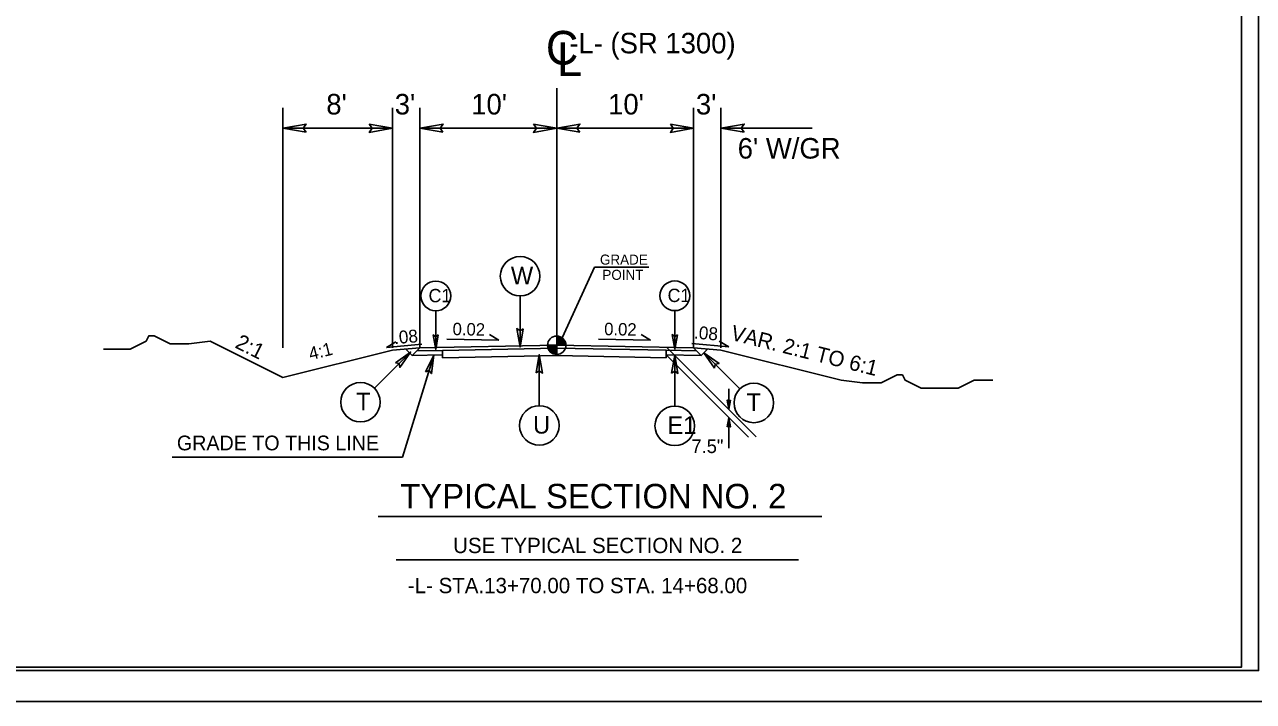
# Model space of a CAD drawing. Extents: x 1818040 to 1825768, y 638918 to 648046.
# Drawn here: x 1821171 to 1822069, y 645383 to 645878 of the extents above; entities that cross this region are included whole.
import ezdxf

# ---------------------------------------------------------------- set-up
doc = ezdxf.new("R2010")
doc.units = 0
for name, color, linetype in [('Old_Level_1', 7, 'Continuous'), ('Prop Dimension', 7, 'Continuous'), ('Prop Dimension Text', 7, 'Continuous'), ('Sheet Plot Border Inside CELL', 7, 'Continuous'), ('Sheet Plot Border Outside CELL', 7, 'Continuous'), ('Sheet Typical CELL', 7, 'Continuous'), ('Typical Grade Point Symbol CELL', 7, 'Continuous'), ('Typical ID Circle CELL', 7, 'Continuous'), ('Typical Pavement Slope CELL', 7, 'Continuous'), ('Typical Pavement Slope Information CELL', 7, 'Continuous'), ('Typical Shoulder Slope CELL', 7, 'Continuous'), ('Typical Slope Point Local CELL', 7, 'Continuous'), ('Typical Terminator CELL', 7, 'Continuous'), ('Typical Text Centerline CELL', 7, 'Continuous'), ('Typical Text General CELL', 7, 'Continuous'), ('Typical Text Grade Point CELL', 7, 'Continuous'), ('Typical Text ID Circle CELL', 7, 'Continuous'), ('Typical Text Label CELL', 7, 'Continuous')]:
    doc.layers.add(name, color=color, linetype=linetype)

msp = doc.modelspace()

# ---------------------------------------------------------------- linework, layer by layer
at = {"layer": 'Old_Level_1'}
for p, q in [((1821359.76, 645641.59), (1821359.76, 645817.04)), ((1821459.76, 645641.59), (1821454.23, 645636.06)), ((1821476.24, 645639.84), (1821559.76, 645641.51)), ((1821639.72, 645639.91), (1821559.76, 645641.51)), ((1821640.27, 645641.96), (1821705.42, 645576.81)), ((1821659.76, 645641.59), (1821665.29, 645636.06)), ((1821469.96, 645636.39), (1821447.16, 645561.85)), ((1821454.23, 645636.06), (1821449.55, 645640.74)), ((1821454.23, 645636.06), (1821476.24, 645636.5)), ((1821457.63, 645639.46), (1821476.24, 645639.84)), ((1821476.24, 645639.84), (1821476.24, 645634.41)), ((1821476.24, 645634.41), (1821559.76, 645636.08)), ((1821639.72, 645634.48), (1821559.76, 645636.08)), ((1821661.89, 645639.46), (1821639.72, 645639.91)), ((1821639.72, 645639.91), (1821639.72, 645634.48)), ((1821639.72, 645636.57), (1821699.84, 645576.45)), ((1821665.29, 645636.06), (1821639.72, 645636.57)), ((1821665.29, 645636.06), (1821669.97, 645640.74)), ((1821685.49, 645611.63), (1821685.49, 645596.8)), ((1821685.49, 645590.68), (1821685.49, 645568.36)), ((1821447.16, 645561.85), (1821278.76, 645561.85))]:
    msp.add_line(p, q, dxfattribs=at)
at = {"layer": 'Prop Dimension'}
for p, q in [((1821559.76, 645643.59), (1821559.76, 645831.25)), ((1821439.76, 645641.59), (1821439.76, 645817.04)), ((1821459.76, 645641.59), (1821459.76, 645817.04)), ((1821659.76, 645641.59), (1821659.76, 645817.04)), ((1821679.76, 645641.59), (1821679.76, 645817.04)), ((1821439.76, 645802.04), (1821359.76, 645802.04)), ((1821559.76, 645802.04), (1821459.76, 645802.04)), ((1821559.76, 645802.04), (1821659.76, 645802.04)), ((1821679.76, 645802.04), (1821746.29, 645802.04))]:
    msp.add_line(p, q, dxfattribs=at)
at = {"layer": 'Sheet Plot Border Inside CELL'}
msp.add_lwpolyline([(1822072.43, 646461.05), (1820405.93, 646461.05), (1820405.93, 645405.95), (1822072.43, 645405.95)], close=True, dxfattribs=at)
at = {"layer": 'Sheet Plot Border Outside CELL'}
msp.add_lwpolyline([(1822076.93, 646483.5), (1820392.93, 646483.5), (1820392.93, 645383.5), (1822076.93, 645383.5)], close=True, dxfattribs=at)
at = {"layer": 'Sheet Typical CELL'}
msp.add_line((1820392.93, 645383.5), (1822076.93, 645383.5), dxfattribs=at)
msp.add_lwpolyline([(1822059.93, 646458.5), (1820559.93, 646458.5), (1820559.93, 645408.5), (1822059.93, 645408.5)], close=True, dxfattribs=at)
at = {"layer": 'Typical Grade Point Symbol CELL'}
for p, q in [((1821559.76, 645643.59), (1821559.76, 645650.3)), ((1821553.05, 645643.59), (1821559.76, 645643.59)), ((1821559.74, 645636.88), (1821559.76, 645643.59)), ((1821559.76, 645643.59), (1821559.74, 645636.88)), ((1821566.47, 645643.59), (1821559.76, 645643.59))]:
    msp.add_line(p, q, dxfattribs=at)
for points in [[(1821559.82, 645650.3), (1821559.82, 645650.3), (1821559.82, 645643.59)], [(1821559.95, 645650.3), (1821559.95, 645643.59)], [(1821560.09, 645650.29), (1821560.09, 645643.59)], [(1821560.22, 645650.29), (1821560.22, 645643.59)], [(1821560.36, 645650.27), (1821560.36, 645643.59)], [(1821560.49, 645650.26), (1821560.49, 645643.59)], [(1821560.63, 645650.24), (1821560.63, 645643.59)], [(1821560.76, 645650.23), (1821560.76, 645643.59)], [(1821560.89, 645650.22), (1821560.89, 645643.59)], [(1821561.03, 645650.19), (1821561.03, 645643.59)], [(1821561.16, 645650.15), (1821561.16, 645643.59)], [(1821561.3, 645650.13), (1821561.3, 645643.59)], [(1821561.43, 645650.1), (1821561.43, 645643.59)], [(1821561.56, 645650.05), (1821561.56, 645643.59)], [(1821561.7, 645650.02), (1821561.7, 645643.59)], [(1821561.83, 645649.98), (1821561.83, 645643.59)], [(1821561.97, 645649.93), (1821561.97, 645643.59)], [(1821562.1, 645649.89), (1821562.1, 645643.59)], [(1821562.24, 645649.83), (1821562.24, 645643.59)], [(1821562.37, 645649.77), (1821562.37, 645643.59)], [(1821553.08, 645643.59), (1821553.08, 645642.86)], [(1821553.21, 645643.59), (1821553.21, 645642.07)], [(1821553.34, 645643.59), (1821553.34, 645641.59)], [(1821553.48, 645643.59), (1821553.48, 645641.19)], [(1821553.61, 645643.59), (1821553.61, 645640.88)], [(1821553.75, 645643.59), (1821553.75, 645640.59)], [(1821553.88, 645643.59), (1821553.88, 645640.34)], [(1821554.02, 645643.59), (1821554.02, 645640.1)], [(1821554.15, 645643.59), (1821554.15, 645639.89)], [(1821554.28, 645643.59), (1821554.28, 645639.7)], [(1821554.42, 645643.59), (1821554.42, 645639.52)], [(1821554.55, 645643.59), (1821554.55, 645639.35)], [(1821554.69, 645643.59), (1821554.69, 645639.19)], [(1821554.82, 645643.59), (1821554.82, 645639.04)], [(1821554.96, 645643.59), (1821554.96, 645638.89)], [(1821555.09, 645643.59), (1821555.09, 645638.76)], [(1821555.22, 645643.59), (1821555.22, 645638.64)], [(1821555.36, 645643.59), (1821555.36, 645638.52)], [(1821555.49, 645643.59), (1821555.49, 645638.4)], [(1821555.63, 645643.59), (1821555.63, 645638.29)], [(1821555.76, 645643.59), (1821555.76, 645638.19)], [(1821555.9, 645643.59), (1821555.9, 645638.1)], [(1821556.03, 645643.59), (1821556.03, 645638.01)], [(1821556.16, 645643.59), (1821556.16, 645637.92)], [(1821556.3, 645643.59), (1821556.3, 645637.83)], [(1821556.43, 645643.59), (1821556.43, 645637.76)], [(1821556.57, 645643.59), (1821556.57, 645637.68)], [(1821556.7, 645643.59), (1821556.7, 645637.61)], [(1821556.84, 645643.59), (1821556.84, 645637.55)], [(1821556.97, 645643.59), (1821556.97, 645637.49)], [(1821557.1, 645643.59), (1821557.1, 645637.43)], [(1821557.24, 645643.59), (1821557.24, 645637.37)], [(1821557.37, 645643.59), (1821557.37, 645637.31)], [(1821557.51, 645643.59), (1821557.51, 645637.26)], [(1821557.64, 645643.59), (1821557.64, 645637.22)], [(1821557.78, 645643.59), (1821557.78, 645637.18)], [(1821557.91, 645643.59), (1821557.91, 645637.15)], [(1821558.04, 645643.59), (1821558.04, 645637.1)], [(1821558.18, 645643.59), (1821558.18, 645637.07)], [(1821558.31, 645643.59), (1821558.31, 645637.04)], [(1821558.45, 645643.59), (1821558.45, 645637.01)], [(1821558.58, 645643.59), (1821558.58, 645636.98)], [(1821558.72, 645643.59), (1821558.72, 645636.97)], [(1821558.85, 645643.59), (1821558.85, 645636.94)], [(1821558.98, 645643.59), (1821558.98, 645636.92)], [(1821559.12, 645643.59), (1821559.12, 645636.91)], [(1821559.25, 645643.59), (1821559.25, 645636.89)], [(1821559.39, 645643.59), (1821559.39, 645636.89)], [(1821559.52, 645643.59), (1821559.52, 645636.88)], [(1821559.66, 645643.59), (1821559.66, 645636.88), (1821559.66, 645636.88)], [(1821562.51, 645649.71), (1821562.51, 645643.59)], [(1821562.64, 645649.65), (1821562.64, 645643.59)], [(1821562.77, 645649.59), (1821562.77, 645643.59)], [(1821562.91, 645649.51), (1821562.91, 645643.59)], [(1821563.04, 645649.44), (1821563.04, 645643.59)], [(1821563.18, 645649.36), (1821563.18, 645643.59)], [(1821563.31, 645649.29), (1821563.31, 645643.59)], [(1821563.44, 645649.2), (1821563.44, 645643.59)], [(1821563.58, 645649.11), (1821563.58, 645643.59)], [(1821563.71, 645649.01), (1821563.71, 645643.59)], [(1821563.85, 645648.92), (1821563.85, 645643.59)], [(1821563.98, 645648.81), (1821563.98, 645643.59)], [(1821564.12, 645648.69), (1821564.12, 645643.59)], [(1821564.25, 645648.57), (1821564.25, 645643.59)], [(1821564.38, 645648.45), (1821564.38, 645643.59)], [(1821564.52, 645648.32), (1821564.52, 645643.59)], [(1821564.65, 645648.19), (1821564.65, 645643.59)], [(1821564.79, 645648.04), (1821564.79, 645643.59)], [(1821564.92, 645647.87), (1821564.92, 645643.59)], [(1821565.06, 645647.71), (1821565.06, 645643.59)], [(1821565.19, 645647.53), (1821565.19, 645643.59)], [(1821565.33, 645647.34), (1821565.33, 645643.59)], [(1821565.46, 645647.13), (1821565.46, 645643.59)], [(1821565.59, 645646.9), (1821565.59, 645643.59)], [(1821565.73, 645646.66), (1821565.73, 645643.59)], [(1821565.86, 645646.38), (1821565.86, 645643.59)], [(1821566, 645646.07), (1821566, 645643.59)], [(1821566.13, 645645.69), (1821566.13, 645643.59)], [(1821566.26, 645645.23), (1821566.26, 645643.59)], [(1821566.4, 645644.55), (1821566.4, 645643.59)]]:
    msp.add_lwpolyline(points, dxfattribs=at)
msp.add_circle((1821559.75, 645643.59), 6.71, dxfattribs=at)
for start, end in [(359.99048, 89.99048), (179.99048, 269.99048)]:
    msp.add_arc((1821559.75, 645643.59), 6.71, start, end, dxfattribs=at)
at = {"layer": 'Typical ID Circle CELL'}
for p, q in [((1821532.99, 645679.56), (1821532.99, 645642.28)), ((1821471.45, 645668.68), (1821471.45, 645640.57)), ((1821646.06, 645668.86), (1821646.06, 645640.75)), ((1821426.6, 645612.18), (1821452.97, 645638.54)), ((1821547.06, 645599.43), (1821547.06, 645633.88)), ((1821645.96, 645599.17), (1821645.96, 645633.62)), ((1821693.55, 645611.64), (1821667.18, 645638))]:
    msp.add_line(p, q, dxfattribs=at)
for centre, radius in [((1821532.99, 645693.98), 14.43), ((1821471.45, 645679.56), 10.88), ((1821646.06, 645679.73), 10.88), ((1821416.41, 645601.97), 14.43), ((1821703.74, 645601.44), 14.43), ((1821547.06, 645585.01), 14.43), ((1821645.96, 645584.75), 14.43)]:
    msp.add_circle(centre, radius, dxfattribs=at)
at = {"layer": 'Typical Pavement Slope CELL'}
for p in [(1821459.76, 645641.59), (1821659.76, 645641.59)]:
    msp.add_line(p, (1821559.76, 645643.59), dxfattribs=at)
at = {"layer": 'Typical Pavement Slope Information CELL'}
for p, q in [((1821517.45, 645647.34), (1821510.69, 645651.42)), ((1821628.18, 645647.34), (1821621.42, 645651.42)), ((1821435.43, 645641.89), (1821442.33, 645646.06)), ((1821461.26, 645644.39), (1821435.43, 645641.89)), ((1821517.45, 645647.34), (1821479.48, 645648.1)), ((1821628.18, 645647.34), (1821590.2, 645648.1)), ((1821685.38, 645642.36), (1821658.5, 645644.96)), ((1821685.38, 645642.36), (1821678.49, 645646.53))]:
    msp.add_line(p, q, dxfattribs=at)
at = {"layer": 'Typical Shoulder Slope CELL'}
for p, q in [((1821439.76, 645639.92), (1821459.76, 645641.59)), ((1821679.76, 645639.92), (1821659.76, 645641.59))]:
    msp.add_line(p, q, dxfattribs=at)
at = {"layer": 'Typical Slope Point Local CELL'}
for p, q in [((1821306.56, 645646.52), (1821359.76, 645619.92)), ((1821439.76, 645639.92), (1821359.76, 645619.92)), ((1821679.76, 645639.92), (1821767.51, 645617.99))]:
    msp.add_line(p, q, dxfattribs=at)
for points in [[(1821306.56, 645646.52), (1821291, 645644.59), (1821287.11, 645644.59), (1821281.27, 645644.59), (1821277.38, 645644.59), (1821273.49, 645646.52), (1821269.6, 645648.48), (1821265.71, 645650.43), (1821261.82, 645650.43), (1821259.86, 645646.52), (1821255.97, 645644.59), (1821252.08, 645642.63), (1821248.19, 645640.7), (1821244.3, 645640.7), (1821240.41, 645640.7), (1821236.52, 645640.7), (1821232.63, 645640.7), (1821228.74, 645640.7)], [(1821767.51, 645617.99), (1821783.07, 645616.05), (1821786.96, 645616.05), (1821792.8, 645616.05), (1821796.69, 645616.05), (1821800.58, 645617.99), (1821804.47, 645619.94), (1821808.36, 645621.89), (1821812.25, 645621.89), (1821814.21, 645617.99), (1821818.1, 645616.05), (1821821.99, 645614.1), (1821825.88, 645612.16), (1821829.77, 645612.16), (1821833.66, 645612.16), (1821837.55, 645612.16), (1821841.44, 645612.16), (1821845.33, 645612.16), (1821849.22, 645612.16), (1821853.11, 645612.16), (1821857, 645614.1), (1821860.89, 645616.05), (1821864.78, 645617.99), (1821870.62, 645617.99), (1821874.51, 645617.99), (1821878.4, 645617.99)]]:
    msp.add_lwpolyline(points, dxfattribs=at)
at = {"layer": 'Typical Terminator CELL'}
for points in [[(1821376.63, 645799.13), (1821359.76, 645802.04), (1821376.73, 645805.04), (1821374.57, 645802.04)], [(1821422.88, 645804.95), (1821439.76, 645802.04), (1821422.79, 645799.04), (1821424.95, 645802.04)], [(1821476.63, 645799.13), (1821459.76, 645802.04), (1821476.73, 645805.04), (1821474.57, 645802.04)], [(1821542.88, 645804.95), (1821559.76, 645802.04), (1821542.79, 645799.04), (1821544.95, 645802.04)], [(1821576.63, 645799.13), (1821559.76, 645802.04), (1821576.73, 645805.04), (1821574.57, 645802.04)], [(1821642.88, 645804.95), (1821659.76, 645802.04), (1821642.79, 645799.04), (1821644.95, 645802.04)], [(1821696.63, 645799.13), (1821679.76, 645802.04), (1821696.73, 645805.04), (1821694.57, 645802.04)], [(1821473.26, 645651.12), (1821471.45, 645640.57), (1821469.57, 645651.18), (1821471.45, 645649.83)], [(1821535.29, 645655.63), (1821532.99, 645642.28), (1821530.62, 645655.71), (1821532.99, 645654)], [(1821647.88, 645651.3), (1821646.06, 645640.75), (1821644.19, 645651.35), (1821646.06, 645650.01)], [(1821441.9, 645630.72), (1821452.97, 645638.54), (1821445.15, 645627.36), (1821444.68, 645630.25)], [(1821463.9, 645624.26), (1821469.97, 645636.38), (1821468.36, 645622.83), (1821466.58, 645625.15)], [(1821544.76, 645623.36), (1821547.06, 645636.71), (1821549.43, 645623.28), (1821547.06, 645624.99)], [(1821643.66, 645623.09), (1821645.96, 645636.45), (1821648.33, 645623.02), (1821645.96, 645624.72)], [(1821675, 645626.93), (1821667.18, 645638), (1821678.35, 645630.18), (1821675.47, 645629.71)], [(1821686.69, 645603.46), (1821685.49, 645596.8), (1821684.36, 645603.52), (1821685.54, 645602.66)], [(1821684.36, 645584), (1821685.49, 645590.68), (1821686.7, 645583.97), (1821685.51, 645584.82)]]:
    msp.add_lwpolyline(points, close=True, dxfattribs=at)
at = {"layer": 'Typical Text Grade Point CELL'}
for q in [(1821561.3, 645643.59), (1821627.07, 645700.69)]:
    msp.add_line((1821587.27, 645700.69), q, dxfattribs=at)
at = {"layer": 'Typical Text Label CELL'}
for p, q in [((1821429.26, 645518.46), (1821753.32, 645518.46)), ((1821442.57, 645486.91), (1821736.42, 645486.91))]:
    msp.add_line(p, q, dxfattribs=at)

# ---------------------------------------------------------------- texts
at = {"layer": 'Prop Dimension Text'}
for s, height, p in [('-L- (SR 1300)', 15, (1821568.95, 645856.7)), ("8'", 15, (1821391.45, 645812.1)), ("3'", 15, (1821441.45, 645812.1)), ("10'", 15, (1821497.31, 645812.1)), ("10'", 15, (1821597.31, 645812.1)), ("3'", 15, (1821661.45, 645812.1)), ("6' W/GR", 15, (1821691.97, 645779.89)), ('7.5"', 10, (1821658.18, 645564.83))]:
    msp.add_text(s, height=height, dxfattribs=at).set_placement(p)
at = {"layer": 'Typical Pavement Slope Information CELL'}
for p in [(1821483.64, 645650.97), (1821594.36, 645650.97)]:
    msp.add_text('0.02 ', height=9.107, rotation=358.85426, dxfattribs=at).set_placement(p)
at = {"layer": 'Typical Slope Point Local CELL'}
for s, rotation, p in [('.08', 4.76147, (1821441.36, 645644.39)), ('.08', 355.23853, (1821659.77, 645648.47)), ('4:1', 14.03624, (1821379.92, 645632.62))]:
    msp.add_text(s, height=9.373, rotation=rotation, dxfattribs=at).set_placement(p)
at = {"layer": 'Typical Text Centerline CELL'}
msp.add_text('C', height=24.6, dxfattribs=at).set_placement((1821551.83, 645848.51))
msp.add_text('L', height=24.62, rotation=359.9469, dxfattribs=at).set_placement((1821560.01, 645840.11))
at = {"layer": 'Typical Text General CELL'}
for s, height, rotation, p in [('2:1 ', 11.19, 333.43495, (1821324.09, 645642.18)), ('VAR. 2:1 TO 6:1', 11.1896, 345.96376, (1821686.2, 645647.64))]:
    msp.add_text(s, height=height, rotation=rotation, dxfattribs=at).set_placement(p)
msp.add_text('GRADE TO THIS LINE', height=10.742, dxfattribs=at).set_placement((1821282.33, 645566.85))
at = {"layer": 'Typical Text Grade Point CELL'}
for s, height, p in [('GRADE', 7.34, (1821591.36, 645702.45)), ('POINT', 7.34, (1821593.13, 645691.33)), ('-L- STA.13+70.00 TO STA. 14+68.00', 11.1896, (1821451.05, 645462.53))]:
    msp.add_text(s, height=height, dxfattribs=at).set_placement(p)
at = {"layer": 'Typical Text ID Circle CELL'}
for s, height, p in [('W', 12.91, (1821526.27, 645688.04)), ('C1', 9.735, (1821466.13, 645674.96)), ('C1', 9.735, (1821640.74, 645675.13)), ('T', 12.91, (1821413.2, 645596.03)), ('T', 12.91, (1821698.46, 645595.49)), ('U', 12.91, (1821542.5, 645579.07)), ('E1', 12.912, (1821640.63, 645578.8))]:
    msp.add_text(s, height=height, dxfattribs=at).set_placement(p)
at = {"layer": 'Typical Text Label CELL'}
for s, height, p in [('TYPICAL SECTION NO. 2  ', 17.9034, (1821445.5, 645524.46)), ('USE TYPICAL SECTION NO. 2', 11.1896, (1821484.11, 645491.8))]:
    msp.add_text(s, height=height, dxfattribs=at).set_placement(p)

doc.saveas('drawing.dxf')
